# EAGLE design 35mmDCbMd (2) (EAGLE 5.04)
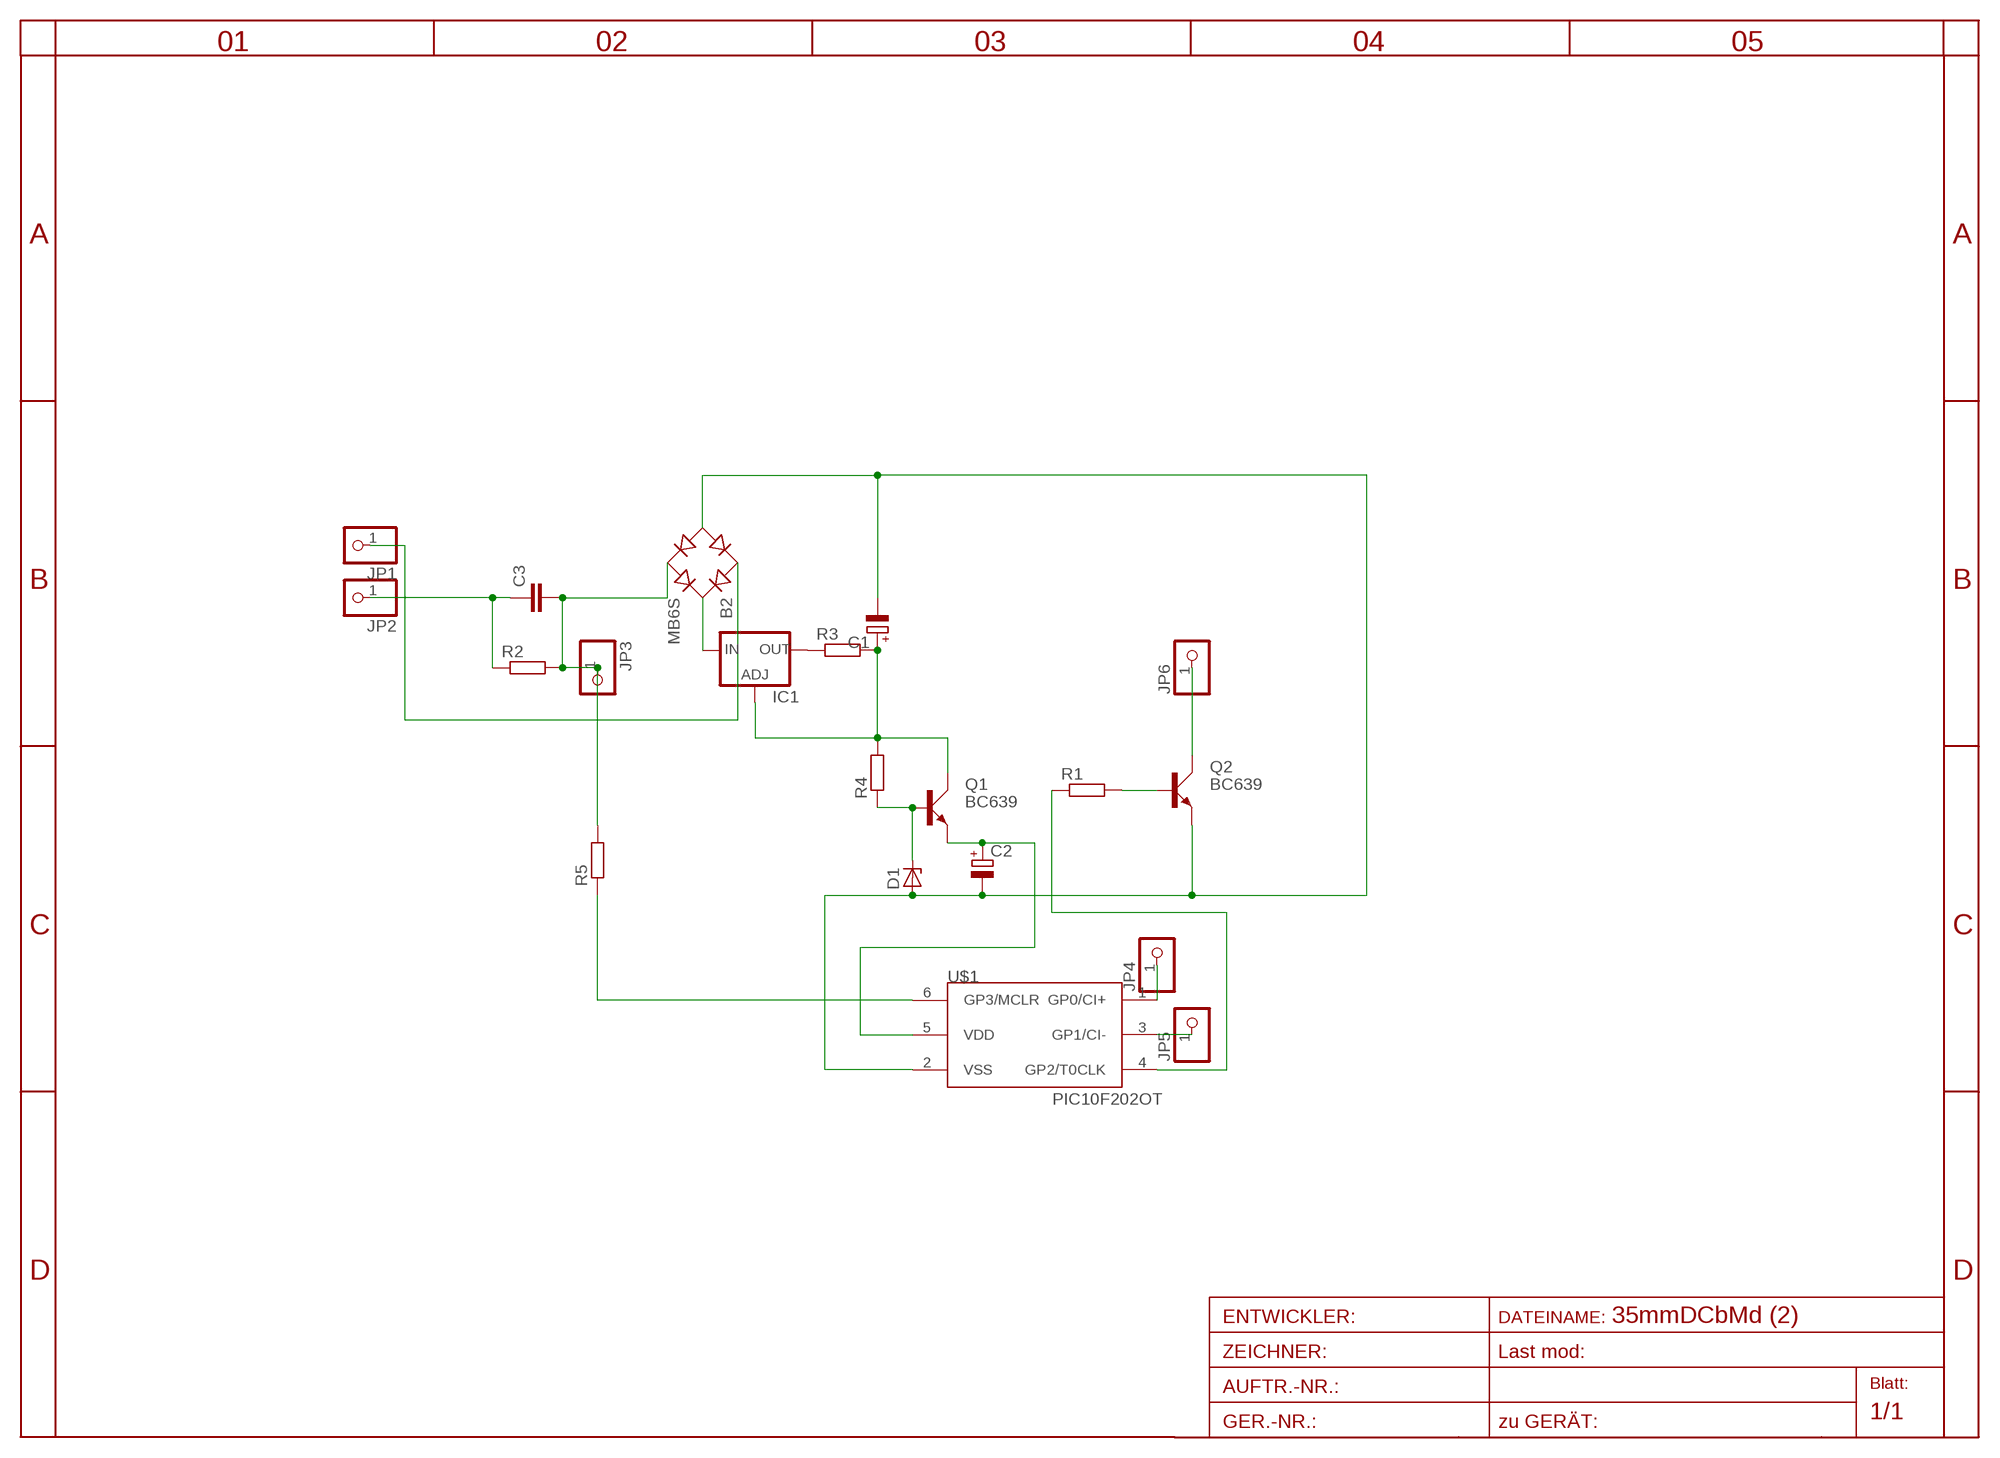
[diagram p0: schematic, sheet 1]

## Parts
B2  MB6S  [SOIC-4]
C1  CPOL-EUE5-8.5  [E5-8,5]
C2  CPOL-EUE2.5-6  [E2,5-6]
C3  C-EU102-064X133  [C102-064X133]
D1  ZENER-DIODEZD-7.5  [ZDIO-7.5]
IC1  LM317LZ  [317L]
JP1  PINHD-1X1  [1X01]
JP2  PINHD-1X1  [1X01]
JP3  PINHD-1X1  [1X01]
JP4  PINHD-1X1  [1X01]
JP5  PINHD-1X1  [1X01]
JP6  PINHD-1X1  [1X01]
Q1  BC639  [SOT54D]
Q2  BC639  [SOT54D]
R1  R-EU_0204/7  [0204/7]
R2  R-EU_R1206  [R1206]
R3  R-EU_R1206  [R1206]
R4  R-EU_0204/7  [0204/7]
R5  R-EU_R1206  [R1206]
U$1  PIC10F202OT  [SOT23-6]

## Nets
AC: B2.~1(AC1) JP1.1
AC+: C3.1 JP2.1 R2.1
MINUS: B2.- C1.- C2.- D1.A Q2.E U$1.2(VSS)
N$1: B2.~2(AC2) C3.2 JP3.1 R2.2 R5.2
N$2: B2.+ IC1.3(IN)
N$3: R5.1 U$1.6(GP3/MCLR)
N$5: IC1.2(OUT) R3.1
N$6: D1.C Q1.B R4.1
N$8: Q2.B R1.2
N$11: R1.1 U$1.4(GP2/T0CLK)
N$12: JP4.1 U$1.1(GP0/CI+)
N$13: JP5.1 U$1.3(GP1/CI-)
N$14: JP6.1 Q2.C
PLUS: C1.+ IC1.1(ADJ) Q1.C R3.2 R4.2
VDD: C2.+ Q1.E U$1.5(VDD)

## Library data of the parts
B2 = rectifier:MB*S: Bridge Rectifier Source: http://www.fairchildsemi.com/ds/MB/MB6S.pdf
C1 = rcl-2:CPOL-EU: POLARIZED CAPACITOR, European symbol
C2 = rcl:CPOL-EU: POLARIZED CAPACITOR, European symbol
C3 = rcl:C-EU: CAPACITOR, European symbol
D1 = diode-1:ZENER-DIODE: Z-Diode
IC1 = v-reg-3:LM317L: Adjustable Voltage Regulator, 1.2V to 37V, 100mA
JP1-JP6 = pinhead:PINHD-1X1: PIN HEADER
Q1 Q2 = transistor-small-signal:BC639: NPN TRANSISTOR
R1-R5 = rcl:R-EU_: RESISTOR, European symbol
U$1 = microchip-5:PIC10F2*: uPC nW 0,25/0,5k Program Flash memory Comparator

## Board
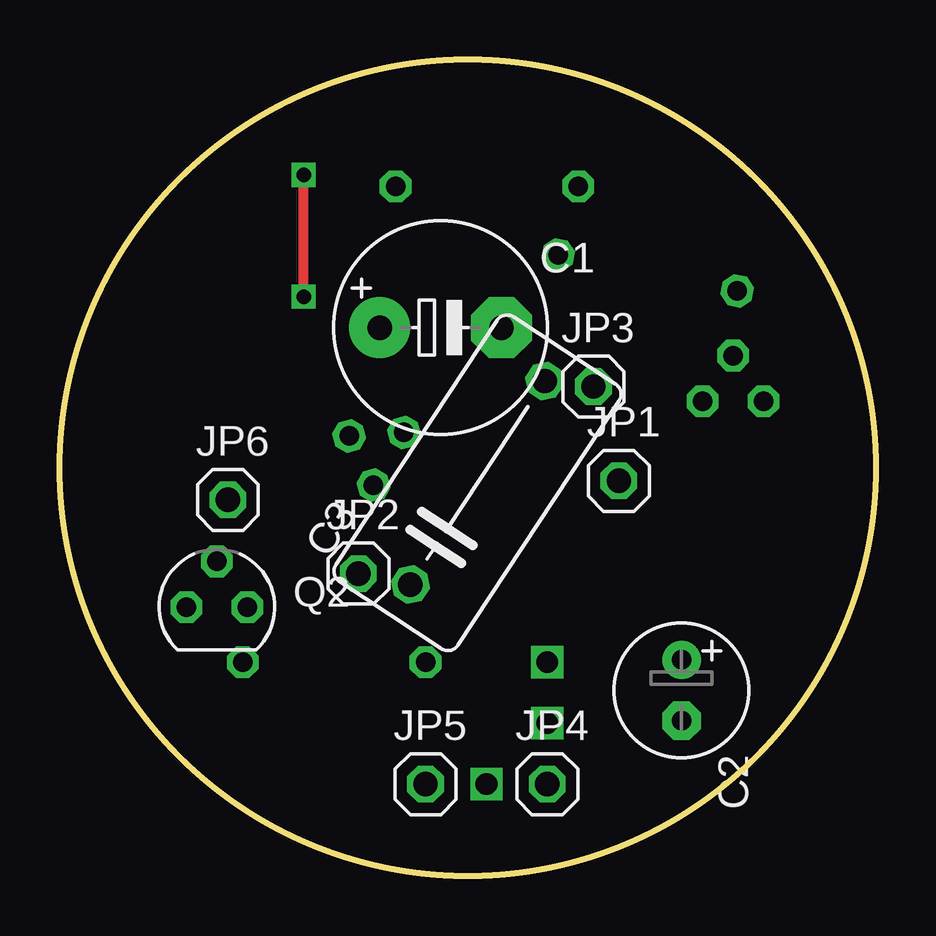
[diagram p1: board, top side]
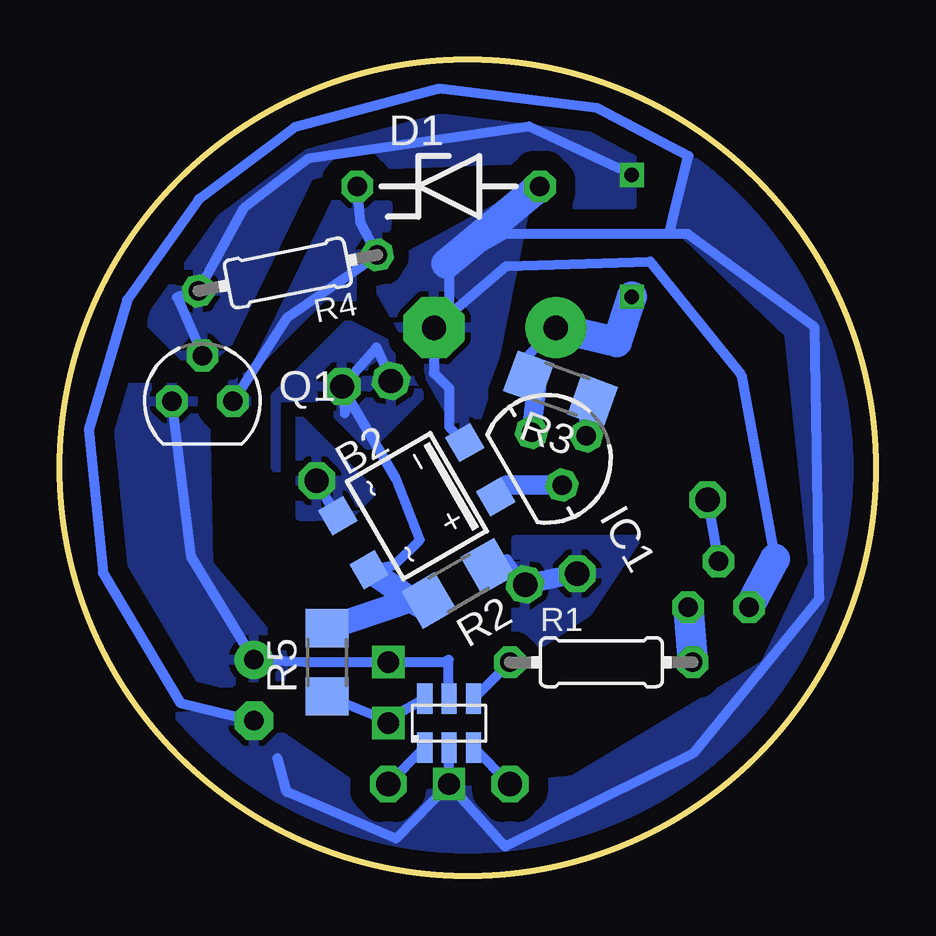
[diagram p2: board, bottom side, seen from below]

Size 34 x 34 mm. Coordinates in mm from the lower left corner, seen from the top.
Outline: circle at 17,17 radius 17
Copper layers (1*16): Top 0.035mm / dielectric 1.5mm / Bottom 0.035mm
Design rules "default *": minimum track width 10mil, minimum drill 24mil, track to track 8mil, track to pad 8mil, pad to pad 8mil, via to via 8mil, smd to smd 8mil, copper to edge 4mil, drill to drill 8mil, minimum pad ring 10mil, minimum via ring 8mil, stop-mask expansion 4mil, vias tented up to drill 0mil, thermal gap 10mil

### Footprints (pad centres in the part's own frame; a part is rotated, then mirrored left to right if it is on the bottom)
SOIC-4 = smd 1.2 x 1.2: + 1.3,3.05; - -1.3,3.05; ~1 -1.3,-3.05; ~2 1.3,-3.05
E5-8,5 = drill 1.016 pad 2.54 round: + -2.54,0 | drill 1.016 pad 2.54 octagon: - 2.54,0
E2,5-6 = drill 0.813 pad 1.6 round: + -1.27,0 | drill 0.813 pad 1.6 octagon: - 1.27,0
C102-064X133 = drill 1.016 octagon: 1 -5.08,0; 2 5.08,0
ZDIO-7.5 = drill 0.813 octagon: A 3.81,0; C -3.81,0
317L = drill 0.813 octagon: 1 -1.27,0; 2 0,1.905; 3 1.27,0
1X01 = drill 1.016 octagon: 1 0,0
SOT54D = drill 0.813 octagon: B 1.27,0; C 0,1.905; E -1.27,0
0204/7 = drill 0.813 octagon: 1 -3.81,0; 2 3.81,0
R1206 = smd 1.6 x 1.803: 1 -1.422,0; 2 1.422,0
SOT23-6 = smd 0.635 x 1.27: 1 -1.016,-1.016; 2 0,-1.016; 3 1.016,-1.016; 4 1.016,1.016; 5 0,1.016; 6 -1.016,1.016

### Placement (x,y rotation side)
B2  19.12,15.4 300 bottom
C1  15.87,22.84 0 top
C2  25.91,7.72 270 top
C3  17.41,16.37 56.6 top
D1  17.8,28.73 0 bottom
IC1  13.71,17.37 300 bottom
JP1  23.3,16.46 0 top
JP2  12.45,12.59 0 top
JP3  22.24,20.39 0 top
JP4  20.32,3.81 0 top
JP5  15.24,3.81 0 top
JP6  7,15.66 0 top
Q1  28.06,19.77 0 bottom
Q2  6.54,11.19 0 top
R1  11.43,8.89 0 bottom
R2  17.39,12.18 210 bottom
R3  13.13,20.29 160 bottom
R4  24.5,25.12 191.4 bottom
R5  22.86,8.89 90 bottom
U$1  17.78,6.35 0 bottom

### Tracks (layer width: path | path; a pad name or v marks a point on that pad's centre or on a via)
AC
  Bottom 0.406: B2.~1 22.44,15 JP1.1
  pour Bottom (isolate 0.61): 21,16 24,19 24,15 22,15
AC+
  Bottom 0.406: R2.1 15.35,13.19 C3.1
  Bottom 0.813: JP2.1 C3.1
  pour Bottom (isolate 0.61): 10,14 15,14 15,9 12,11
MINUS  (via drill 0.9)
  Bottom 0.406: v17.78,3.81 15.44,1.2 7.62,5.08 2.34,11.56 2.54,22.86 7.82,26.74 8.6,26.74 | v17.78,3.81 20,1.54 24.55,3.49 24.93,4.89 | v17.78,3.81 U$1.2 | 17.78,25.4 17.89,25.51 | 17.78,25.4 17.78,23.46 C1.- | 8.6,26.74 15.44,26.74 17.78,25.4 | C1.- 18.41,20.95 17.78,20.32 17.78,18.7 B2.- | 4.2,13.2 5.6,20.86 9.4,25.6 15.4,25.4 C1.- | C2.- 29,7.2 32.2,12.6 32.8,18.6 31.2,24 28.2,28.2 24.2,31.2 18.2,32.8 11.6,32 7.8,30 8.4,27.6 8.6,26.74
  Bottom 1.27: 17.89,25.51 D1.A | 4.2,13.2 Q2.E
  pour Bottom (isolate 0.61, rank 2): 16,21 14.46,28.54 21,25 17,18
  pour Bottom (isolate 0.813, rank 4): 5.08,27.94 0.8,21.2 0.6,13.4 5,5.2 11.4,1.2 17.2,0.4 24.2,1.8 29.8,6.6 26.2,6.8 21,3.2 12.6,4 4.6,8.8 2.6,13 3.6,22.6 8.4,27.2 7.6,29.8
N$1
  Bottom 0.406: C3.2 20.81,22.01 JP3.1 | JP3.1 22.12,19.27 | R2.2 19.02,11.25 19.36,11.5 | B2.~2 20.05,12.95 19,14 20,16.55 JP3.1
  Bottom 1.016: 19.02,11.25 B2.~2 | 19.36,11.5 R5.2
  pour Bottom (isolate 0.61, rank 2): 20,22 19,20 22,17 25,17 25,20 22,23
N$2
  Bottom 0.406: IC1.3 13.36,16.39 | 15.36,16.27 B2.+
  Bottom 0.813: IC1.3 15.36,16.27
N$3
  Bottom 0.406: U$1.6 20.4,6.46 R5.1
N$5
  Bottom 0.406: R3.1 11.86,19.39
  Bottom 0.813: 11.86,19.39 IC1.2
N$6
  Bottom 0.406: D1.C 21.48,27.21 R4.1 24.53,23.27 Q1.B
  pour Bottom (isolate 0.813, rank 4): 20.32,27.94 20.6,25 26.4,19.2 27,20 24,28
N$7  (via drill 0.9)
  other vias: 20.32,8.89
N$8
  Bottom 1.27: R1.2 Q2.B
N$11
  Bottom 0.406: U$1.4 R1.1
N$12
  Bottom 0.406: JP4.1 U$1.1
N$13
  Bottom 0.406: JP5.1 U$1.3
N$14
  Bottom 0.406: Q2.C JP6.1
N$15  (via drill 0.9)
  other vias: 20.32,6.35
PLUS  (via drill 0.6)
  Top 0.406: v10.16,24.13 v10.16,29.21
  Bottom 0.406: 14.14,20.32 R3.2 14.46,21.7 C1.+ | Q1.C 29.12,24.11 R4.2 26.34,27.82 23.66,29.88 14.44,31.22 v10.16,29.21
  Bottom 0.813: IC1.1 14.14,20.32
  Bottom 1.27: C1.+ 10.79,22.23 v10.16,24.13
  pour Bottom (isolate 0.813): 10.16,27.94 10.16,33.02 23.98,33.02 31.2,25.8 31.2,24 28.4,21.2 28,21.4 27,22.2 23.6,29.2 22,29.6 14.6,29.86 14.4,27.6
VDD
  Bottom 0.406: Q1.E 28.53,13.3 C2.+ 23.8,8.89 18,8.89 17.8,9 17.8,7.39 U$1.5
  pour Bottom (isolate 0.813, rank 3): 27.94,20.32 33.02,20.32 32.82,12.9 30.48,7.62 24,8.4 27.8,13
